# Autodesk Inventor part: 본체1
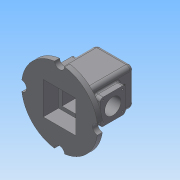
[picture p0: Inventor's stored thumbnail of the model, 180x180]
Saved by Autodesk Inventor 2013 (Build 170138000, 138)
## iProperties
Created: 2018-07
Part Number: 본체1
Material: 일반
Document SubType Name: Modeling
Designer: Administrator
Density: 1 g/cm^3
Author: Administrator
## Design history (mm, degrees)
node "작업 평면1"
sketch "스케치13"
  geometry: C1 r 75 at (0, 0); 1 further point
  constraints: 1 centre point, 1 coincident
  dimensions: "d63" = 150 diameter of C1
extrude "돌출10" join sketch "스케치13" distance "d64" = 10; taper "d65" = 0 deg
sketch "스케치14"
  geometry: C1 r 75 at (0, 0) reference; C2 r 10 at (75, 0); 2 further points
  constraints: 2 horizontal alignment, 1 centre point, 2 other
  dimensions: "d67" = 20 diameter of C2; "d68" = 75 distance of C1.centre C2.centre
extrude "돌출11" cut sketch "스케치14" distance "d69" = 10; taper "d70" = 0 deg
sketch "스케치17"
  geometry: L1 (-32, 32)-(32, 32); L2 (32, 32)-(32, -32); L3 (32, -32)-(-32, -32); L4 (-32, -32)-(-32, 32); A1 r 5 centre (0, 75) between (-4.997, 74.833) and (4.997, 74.833) reference; A2 r 75 centre (0, 0) between (74.333, 9.978) and (74.333, -9.978) reference; A3 r 5 centre (-75, 0) between (-74.833, -4.997) and (-74.833, 4.997) reference; A4 r 75 centre (0, 0) between (74.333, 9.978) and (74.333, -9.978) reference; A5 r 5 centre (0, -75) between (4.997, -74.833) and (-4.997, -74.833) reference; A6 r 75 centre (0, 0) between (74.333, 9.978) and (74.333, -9.978) reference; A7 r 10 centre (75, 0) between (74.333, 9.978) and (74.333, -9.978) reference; A8 r 75 centre (0, 0) between (74.333, 9.978) and (74.333, -9.978) reference; 2 further points
  constraints: 8 end point, 2 midpoint, 2 parallel, 1 horizontal, 1 horizontal alignment, 1 perpendicular, 1 vertical alignment
  dimensions: "d84" = 64 distance of L2.end L3.end; "d85" = 64 distance of L1.end L2.end
node "작업 평면4"
sketch "스케치19"
  geometry: A1 r 10 centre (75, 0) between (74.333, 9.978) and (74.333, -9.978) reference; A2 r 75 centre (0, 0) between (74.333, 9.978) and (74.333, -9.978) reference
sketch "스케치20"
  geometry: L1 (-37, 37)-(37, 37); L2 (37, 37)-(37, -37); L3 (37, -37)-(-37, -37); L4 (-37, -37)-(-37, 37); A1 r 75 centre (0, 0) between (74.333, 9.978) and (74.333, -9.978) reference; 2 further points
  constraints: 8 end point, 2 midpoint, 2 parallel, 1 horizontal, 1 horizontal alignment, 1 perpendicular, 1 vertical alignment
  dimensions: "d90" = 74 distance of L1.start L1.end; "d92" = 74 distance of L1.end L2.end
extrude "돌출15" join sketch "스케치20" distance "d93" = 100; taper "d94" = 0 deg
sketch "스케치21"
  geometry: L1 (-20, 20)-(20, 20); L2 (20, 20)-(20, -20); L3 (20, -20)-(-20, -20); L4 (-20, -20)-(-20, 20); 3 further points
  constraints: 8 end point, 2 midpoint, 2 parallel, 1 horizontal, 1 horizontal alignment, 1 perpendicular, 1 vertical alignment
  dimensions: "d95" = 40 distance of L2.end L3.end; "d96" = 40 distance of L1.end L2.end
extrude "돌출16" join sketch "스케치21" distance "d97" = 7; taper "d98" = 0 deg
sketch "스케치22"
  geometry: C1 r 17.5 at (0, 0); 1 further point
  constraints: 1 centre point, 1 coincident
  dimensions: "d99" = 35 diameter of C1
extrude "돌출17" join sketch "스케치22" distance "d100" = 3; taper "d101" = 0 deg
sketch "스케치23"
  geometry: C1 r 17.5 at (0, 0) reference; C2 r 14 at (0, 0)
  constraints: 1 centre point, 1 coincident
  dimensions: "d103" = 28 diameter of C2
extrude "돌출18" cut sketch "스케치23" distance "d104" = 4; taper "d105" = 0 deg
sketch "스케치24"
  geometry: C1 r 14 at (0, 0) reference; C2 r 10.5 at (0, 0)
  constraints: 1 centre point, 1 coincident
  dimensions: "d106" = 21 diameter of C2
extrude "돌출19" cut sketch "스케치24" stored distance "d107" = 4; taper "d108" = 0 deg
sketch "스케치25"
  geometry: L1 (74, 0)-(0, 0) reference; L2 (74, 0)-(74, 100) reference; L3 (0, 100)-(74, 100) reference; L4 (0, 0)-(0, 100) reference; 1 further point
sketch "스케치26"
  geometry: L1 (74, 0)-(0, 0) reference; L2 (74, 0)-(74, 100) reference; L3 (0, 100)-(74, 100) reference; L4 (0, 0)-(0, 100) reference; L5 (-28.238, 0)-(0, 0) reference; L6 (0, 0)-(74, 0) reference; L7 (74, 0)-(102.238, 0) reference; L8 (102.238, 0)-(102.238, -10) reference; L9 (102.238, -10)-(-28.238, -10) reference; L10 (-28.238, -10)-(-28.238, 0) reference; L11 (0, 0)-(0, 100) reference; L12 (0, 100)-(74, 100) reference; L13 (74, 100)-(74, 0) reference; 1 further point
  node "절단 모서리 투영5"
node "작업 평면6"
sketch "스케치27"
  geometry: L1 (-58, 74.333)-(-58, 9.978) reference; C1 r 16 at (-3, 0); 1 further point
  constraints: 1 centre point
  dimensions: "d113" = 32 diameter of C1; "d114" = 55 distance from line of L1 C1.centre
sketch "스케치28"
  geometry: L1 (22, 25)-(-28, 25); L2 (-28, 25)-(-28, -25); L3 (-28, -25)-(22, -25); L4 (22, -25)-(22, 25); L5 (-48, 55.902)-(-48, -55.902) reference; L6 (-48, -55.902)-(-58, -55.902) reference; L7 (-58, -55.902)-(-58, 55.902) reference; L8 (-58, 55.902)-(-48, 55.902) reference; 2 further points
  constraints: 8 end point, 2 parallel, 1 horizontal, 1 horizontal alignment, 1 midpoint, 1 perpendicular
  dimensions: "d115" = 50 distance of L3.end L1.start; "d117" = 50 distance of L2.end L3.end; "d120" = 80 distance between parallel lines of L7 L4
extrude "돌출21" join sketch "스케치28" stored distance "d121" = 4; taper "d122" = 0 deg
extrude "돌출22" cut sketch "스케치27" stored distance "d123" = 4; taper "d124" = 0 deg
sketch "스케치29"
  geometry: L1 (-25, 22)-(-25, -28) reference; L2 (-25, -28)-(25, -28) reference; L3 (25, -28)-(25, 22) reference; L4 (25, 22)-(-25, 22) reference; C1 r 16 at (0, -3) reference; 1 further point
fillet "모깎기1" dims "d125" = 8
fillet "모깎기2" dims "d126" = 8
fillet "모깎기3" dims "d127" = 3
fillet "모깎기4" dims "d128" = 3
fillet "모깎기5" dims "d129" = 3
fillet "모깎기6" dims "d130" = 6
fillet "모깎기7" dims "d131" = 3
sketch "스케치30"
  geometry: L1 (-32, 32)-(32, 32); L2 (32, 32)-(32, -32); L3 (32, -32)-(-32, -32); L4 (-32, -32)-(-32, 32); C1 r 10.5 at (0, 0) reference; A1 r 75 centre (0, 0) between (9.978, -74.333) and (74.333, -9.978) reference; 2 further points
  constraints: 8 end point, 2 midpoint, 2 parallel, 1 horizontal, 1 horizontal alignment, 1 perpendicular, 1 vertical alignment
  dimensions: "d132" = 64 distance of L1.start L1.end; "d135" = 64 distance of L1.end L2.end
extrude "돌출23" cut sketch "스케치30" distance "d136" = 30; taper "d137" = 0 deg
sketch "스케치31"
  geometry: L1 (-25, 25)-(25, 25); L2 (25, 25)-(25, -25); L3 (25, -25)-(-25, -25); L4 (-25, -25)-(-25, 25); C1 r 10.5 at (0, 0) reference; 2 further points
  constraints: 8 end point, 2 midpoint, 2 parallel, 1 horizontal, 1 horizontal alignment, 1 perpendicular, 1 vertical alignment
  dimensions: "d138" = 50 distance of L1.start L1.end; "d140" = 50 distance of L1.end L2.end
extrude "돌출24" cut sketch "스케치31" distance "d141" = 50; taper "d142" = 0 deg
sketch "스케치32"
  geometry: L1 (-32, 32)-(32, 32); L2 (32, 32)-(32, -32); L3 (32, -32)-(-32, -32); L4 (-32, -32)-(-32, 32); C1 r 10.5 at (0, 0) reference; 2 further points
  constraints: 8 end point, 2 midpoint, 2 parallel, 1 horizontal, 1 horizontal alignment, 1 perpendicular, 1 vertical alignment
  dimensions: "d143" = 64 distance of L1.end L2.end; "d145" = 64 distance of L1.start L1.end
extrude "돌출25" cut sketch "스케치32" distance "d146" = 25; taper "d147" = 0 deg
sketch "스케치33"
  geometry: L1 (66, -89)-(66, 0) reference; L2 (46.5, 18)-(11.5, 18) reference; 2 further points
  constraints: 1 other
  dimensions: "d148" = 37 distance from line of L1 point (29, -12); "d149" = 30 distance from line of point (29, -12) L2
feature "엠보싱1" sketch "스케치33" dims "d150" = 0.5, "d151" = 0
sketch "스케치38"
  geometry: A1 r 6 centre (-19, 16) between (-19, 22) and (-25, 16) reference; 2 further points
  constraints: 1 coincident
hole "구멍3" sketch "스케치38" at (-19, 16) diameter "d164" = 3.242; stored, may be unused: countersink angle "d168" = 90 deg, drill point angle "d170" = 118 deg; dims "d165" = 8, "d166" = 4, "d167" = 2, "d169" = 10
fillet "모깎기8" dims "d174" = 3
sketch "스케치39"
  geometry: L1 (37, -31)-(37, -45) reference; L2 (40, -48)-(65, -48) reference; L3 (65, -48)-(65, -58) reference; L4 (65, -58)-(32, -58) reference; L5 (32, -58)-(32, -28) reference; L6 (32, -28)-(25, -28) reference; L7 (25, -28)-(25, -19) reference; L8 (25, -19)-(50, -19) reference; L9 (50, -19)-(50, -28) reference; L10 (50, -28)-(40, -28) reference; L11 (-40, -28)-(-50, -28) reference; L12 (-50, -28)-(-50, -19) reference; L13 (-50, -19)-(-25, -19) reference; L14 (-25, -19)-(-25, -28) reference; L15 (-25, -28)-(-32, -28) reference; L16 (-32, -28)-(-32, -58) reference; L17 (-32, -58)-(-65, -58) reference; L18 (-65, -58)-(-65, -48) reference; L19 (-65, -48)-(-40, -48) reference; L20 (-37, -45)-(-37, -31) reference; L21 (-17.5, 59)-(-17.5, 62) reference; L22 (-17.5, 62)-(-14, 62) reference; L23 (-14, 62)-(-14, 58) reference; L24 (-14, 58)-(-10.5, 58) reference; L25 (-10.5, 58)-(-10.5, 47) reference; L26 (-10.5, 47)-(-29, 47) reference; L27 (-32, 44)-(-32, 22) reference; L28 (-32, 22)-(-25, 22) reference; L29 (-25, 22)-(-25, 13) reference; L30 (-25, 13)-(-50, 13) reference; L31 (-50, 13)-(-50, 22) reference; L32 (-50, 22)-(-40, 22) reference; L33 (-37, 25)-(-37, 44) reference; L34 (-29, 52)-(-23, 52) reference; L35 (-20, 55)-(-20, 59) reference; L36 (-20, 59)-(-17.5, 59) reference; L37 (17.5, 62)-(17.5, 59) reference; L38 (17.5, 59)-(20, 59) reference; L39 (20, 59)-(20, 55) reference; L40 (23, 52)-(29, 52) reference; L41 (37, 44)-(37, 33.671) reference; L42 (37, 33.671)-(37.5, 33.671) reference; L43 (37.5, 33.671)-(37.5, 33.416) reference; L44 (37.5, 33.416)-(37, 33.416) reference; L45 (37, 33.416)-(37, 25) reference; L46 (40, 22)-(50, 22) reference; L47 (50, 22)-(50, 13) reference; L48 (50, 13)-(25, 13) reference; L49 (25, 13)-(25, 22) reference; L50 (25, 22)-(32, 22) reference; L51 (32, 22)-(32, 44) reference; L52 (29, 47)-(10.5, 47) reference; L53 (10.5, 47)-(10.5, 58) reference; L54 (10.5, 58)-(14, 58) reference; L55 (14, 58)-(14, 62) reference; L56 (14, 62)-(17.5, 62) reference; L57 (37, -31)-(37, -45) reference; L58 (40, -48)-(65, -48) reference; L59 (65, -48)-(65, -58) reference; L60 (65, -58)-(32, -58) reference; L61 (32, -58)-(32, -28) reference; L62 (32, -28)-(25, -28) reference; L63 (25, -28)-(25, -19) reference; L64 (25, -19)-(50, -19) reference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; A1 r 3 centre (40, -31) between (40, -28) and (37, -31) reference; A2 r 3 centre (40, -45) between (37, -45) and (40, -48) reference; A3 r 3 centre (-40, -31) between (-37, -31) and (-40, -28) reference; A4 r 3 centre (-40, -45) between (-40, -48) and (-37, -45) reference; A5 r 3 centre (-29, 44) between (-29, 47) and (-32, 44) reference; A6 r 3 centre (-40, 25) between (-40, 22) and (-37, 25) reference; A7 r 8 centre (-29, 44) between (-29, 52) and (-37, 44) reference; A8 r 3 centre (-23, 55) between (-23, 52) and (-20, 55) reference; A9 r 3 centre (23, 55) between (20, 55) and (23, 52) reference; A10 r 8 centre (29, 44) between (37, 44) and (29, 52) reference; A11 r 3 centre (40, 25) between (37, 25) and (40, 22) reference; A12 r 3 centre (29, 44) between (32, 44) and (29, 47) reference; A13 r 3 centre (40, -31) between (40, -28) and (37, -31) reference; A14 r 3 centre (40, -45) between (37, -45) and (40, -48) reference; A15 r 3 centre (-40, -31) between (-37, -31) and (-40, -28) reference; A16 r 3 centre (-40, -45) between (-40, -48) and (-37, -45) reference; A17 r 3 centre (-29, 44) between (-29, 47) and (-32, 44) reference; A18 r 3 centre (-40, 25) between (-40, 22) and (-37, 25) reference; A19 r 8 centre (-29, 44) between (-29, 52) and (-37, 44) reference; A20 r 3 centre (-23, 55) between (-23, 52) and (-20, 55) reference; A21 r 3 centre (23, 55) between (20, 55) and (23, 52) reference; A22 r 8 centre (29, 44) between (37, 44) and (29, 52) reference; A23 r 3 centre (40, 25) between (37, 25) and (40, 22) reference; A24 r 3 centre (29, 44) between (32, 44) and (29, 47) reference; 1 further point
  constraints: 6 end point, 2 collinear, 1 point on line
  dimensions: "d175" = 110 deg angle of L113 L27
extrude "돌출26" cut sketch "스케치39" stored distance "d176" = 60; taper "d177" = 0 deg
sketch "스케치41"
  geometry: L1 (59, 17.5)-(62, 17.5) reference; L2 (62, 17.5)-(62, 14) reference; L3 (62, 14)-(58, 14) reference; L4 (58, 14)-(58, 10.5) reference; L5 (58, 10.5)-(47, 10.5) reference; L6 (47, 10.5)-(47, 29) reference; L7 (44, 32)-(22, 32) reference; L8 (22, 32)-(22, 25) reference; L9 (22, 25)-(-28, 25) reference; L10 (-28, 25)-(-28, 32) reference; L11 (-28, 32)-(-58, 32) reference; L12 (-58, 32)-(-58, 65) reference; L13 (-58, 65)-(-48, 65) reference; L14 (-48, 65)-(-48, 40) reference; L15 (-45, 37)-(44, 37) reference; L16 (52, 29)-(52, 23) reference; L17 (55, 20)-(59, 20) reference; L18 (59, 20)-(59, 17.5) reference; L19 (62, -17.5)-(59, -17.5) reference; L20 (59, -17.5)-(59, -20) reference; L21 (59, -20)-(55, -20) reference; L22 (52, -23)-(52, -29) reference; L23 (44, -37)-(-45, -37) reference; L24 (-48, -40)-(-48, -65) reference; L25 (-48, -65)-(-58, -65) reference; L26 (-58, -65)-(-58, -32) reference; L27 (-58, -32)-(-28, -32) reference; L28 (-28, -32)-(-28, -25) reference; L29 (-28, -25)-(22, -25) reference; L30 (22, -25)-(22, -32) reference; L31 (22, -32)-(44, -32) reference; L32 (47, -29)-(47, -10.5) reference; L33 (47, -10.5)-(58, -10.5) reference; L34 (58, -10.5)-(58, -14) reference; L35 (58, -14)-(62, -14) reference; L36 (62, -14)-(62, -17.5) reference; L37 (22, 32)-(19.452, 25); L38 (19.452, 25)-(22, 25); L39 (22, 25)-(22, 32); A1 r 3 centre (44, 29) between (47, 29) and (44, 32) reference; A2 r 3 centre (-45, 40) between (-48, 40) and (-45, 37) reference; A3 r 8 centre (44, 29) between (52, 29) and (44, 37) reference; A4 r 3 centre (55, 23) between (52, 23) and (55, 20) reference; A5 r 3 centre (55, -23) between (55, -20) and (52, -23) reference; A6 r 8 centre (44, -29) between (44, -37) and (52, -29) reference; A7 r 3 centre (-45, -40) between (-45, -37) and (-48, -40) reference; A8 r 3 centre (44, -29) between (44, -32) and (47, -29) reference; 1 further point
  constraints: 6 end point, 1 collinear, 1 perpendicular, 1 point on line
  dimensions: "d178" = 110 deg angle of L37 L7
extrude "돌출27" cut sketch "스케치41" stored distance "d179" = 60; taper "d180" = 0 deg
node "솔리드2"
pattern_circular "원형 패턴4" dims angle "d110" = 360 deg
mirror "대칭2"
pattern_circular "원형 패턴5" dims angle "d172" = 360 deg
mirror "대칭3"
mirror "대칭4"
mirror "대칭5"
node "절단 모서리 투영2"
node "절단 모서리 투영3"
node "절단 모서리 투영6"
node "절단 모서리 투영10"
node "절단 모서리 투영11"
node "절단 모서리 투영12"
